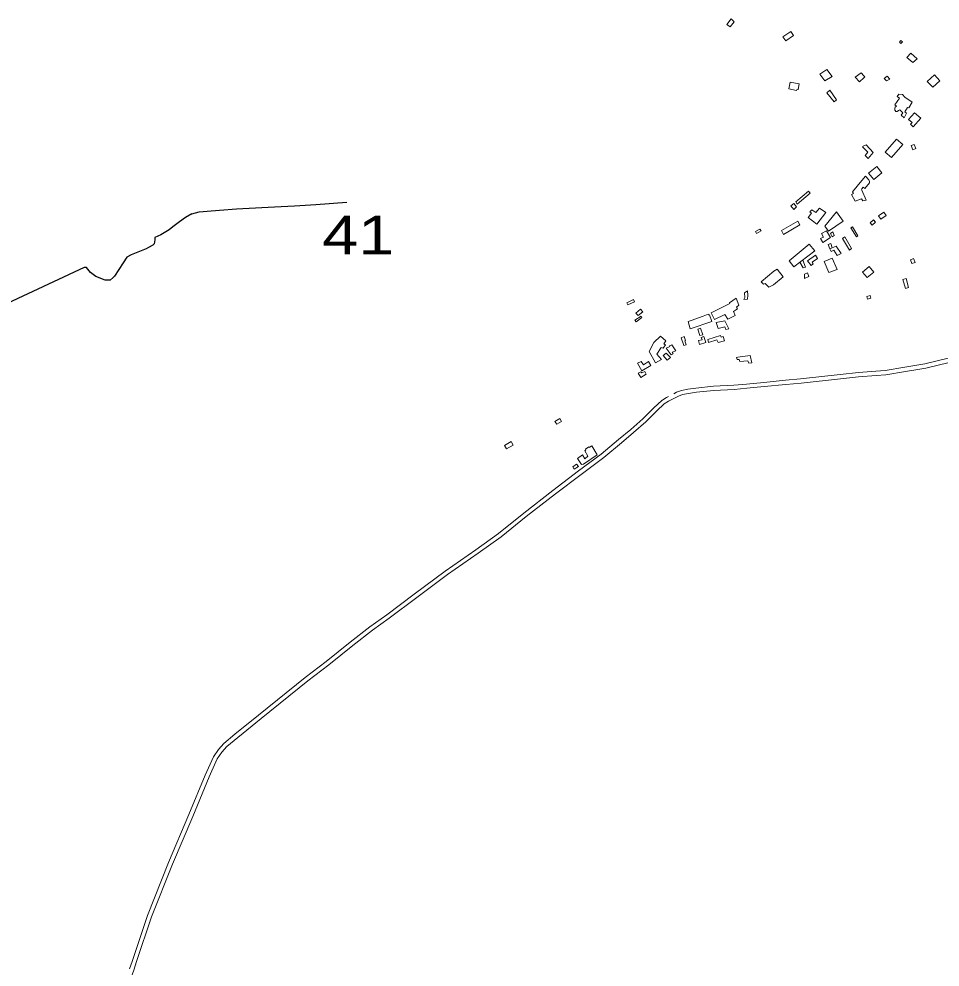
# Model space of a CAD drawing. Extents: x 476989 to 498418, y 4381813 to 4416555.
# Drawn here: x 484337 to 485528, y 4384128 to 4385354 of the extents above; entities that cross this region are included whole.
import ezdxf
from ezdxf.enums import TextEntityAlignment as Align

# ---------------------------------------------------------------- set-up
doc = ezdxf.new("R2010")
doc.units = 0
doc.header["$LTSCALE"] = 20
for name, color, linetype, lineweight in [('13', 7, 'Continuous', 13), ('36', 7, 'Continuous', 13), ('47', 7, 'Continuous', 13), ('6', 7, 'Continuous', 25)]:
    doc.layers.add(name, color=color, linetype=linetype, lineweight=lineweight)

msp = doc.modelspace()

# ---------------------------------------------------------------- linework, layer by layer
at = {"layer": '36'}
for points in [[(485422.69, 4384896.4), (485445.04, 4384898.28), (485457.06, 4384899.22), (485464.89, 4384900.34), (485474.69, 4384902.21), (485508.34, 4384907.79), (485538.44, 4384915.04), (485558.81, 4384919.82), (485586.93, 4384924.38), (485601.44, 4384927.38)], [(485422.62, 4384890.78), (485445.5, 4384892.7), (485457.67, 4384893.65), (485465.81, 4384894.8), (485475.68, 4384896.69), (485509.45, 4384902.29), (485539.74, 4384909.58)], [(484710.84, 4384497.83), (484737.94, 4384518.74), (484768.95, 4384543.65), (484794.34, 4384563.28), (484815.94, 4384578.76), (484851.61, 4384605.75), (484891.48, 4384635.27), (484931.04, 4384662.95), (484960.7, 4384684.23), (484993.21, 4384710.28), (485030.75, 4384739.64), (485063.92, 4384764.85), (485093.47, 4384786.49), (485116.03, 4384805.54), (485131.93, 4384818.81), (485147.77, 4384832.69), (485161.73, 4384847.04), (485171.53, 4384855.86), (485177.07, 4384859.62), (485182.06, 4384861.97), (485189.79, 4384866.01), (485195.1, 4384868.19), (485202.95, 4384869.58), (485213.04, 4384870.95), (485235.55, 4384873.26), (485261.75, 4384874.66), (485278.18, 4384876.14), (485300.64, 4384878.33), (485328.67, 4384881.11), (485348.27, 4384882.97), (485399.25, 4384888.59), (485422.62, 4384890.78)], [(485183.89, 4384869.09), (485187.49, 4384870.96), (485193.57, 4384873.46), (485202.11, 4384874.97), (485212.4, 4384876.37), (485235.13, 4384878.7), (485261.36, 4384880.1), (485277.67, 4384881.57), (485300.11, 4384883.76), (485328.15, 4384886.54), (485347.71, 4384888.4), (485398.68, 4384894.02), (485422.69, 4384896.4)], [(484707.31, 4384502.21), (484734.52, 4384522.99), (484765.58, 4384547.94), (484791.08, 4384567.66), (484812.71, 4384583.16), (484848.35, 4384610.12), (484888.3, 4384639.7), (484927.89, 4384667.41), (484957.41, 4384688.58), (484989.83, 4384714.56), (485027.43, 4384743.96), (485060.66, 4384769.23), (485090.09, 4384790.79), (485112.52, 4384809.73), (485128.38, 4384822.96), (485144.01, 4384836.66), (485157.94, 4384850.98), (485168.16, 4384860.16), (485174.35, 4384864.37), (485176.85, 4384865.55)], [(484707.31, 4384502.21), (484647.11, 4384453.76), (484616.61, 4384429.19), (484602.17, 4384416.91), (484595.22, 4384409.32), (484588.71, 4384399.61), (484578.28, 4384375.87), (484557.06, 4384324.92), (484530.87, 4384263.12), (484503.59, 4384194.75), (484483.62, 4384135.07)], [(484710.84, 4384497.83), (484650.64, 4384449.38), (484620.19, 4384424.86), (484606.08, 4384412.85), (484599.65, 4384405.84), (484593.66, 4384396.89), (484583.45, 4384373.66), (484562.24, 4384322.74), (484536.06, 4384260.98), (484508.87, 4384192.82), (484489.54, 4384135.06)], [(484489.54, 4384135.06), (484485.82, 4384123.95), (484464.73, 4384064.76), (484456.32, 4384037.55), (484452.16, 4384022.11), (484445.88, 4383992.25), (484439.72, 4383943.85), (484434.59, 4383882), (484432.54, 4383857.52), (484431.34, 4383851.22), (484425.3, 4383828.91), (484409.87, 4383774.4), (484390.58, 4383702.73), (484376.62, 4383650.17), (484370.9, 4383630.79), (484368.78, 4383624.62), (484366.56, 4383620.22), (484360.54, 4383612.24), (484358.1, 4383609.8)], [(484483.62, 4384135.07), (484480.51, 4384125.78)]]:
    msp.add_lwpolyline(points, dxfattribs=at)
at = {"layer": '47'}
for p, q in [((485430.73, 4385278.66), (485429.6, 4385277.65)), ((485429.64, 4385279.89), (485430.73, 4385278.66)), ((485431.59, 4385150.48), (485427.01, 4385144.68))]:
    msp.add_line(p, q, dxfattribs=at)
for points in [[(485261.75, 4385350.07), (485256.55, 4385343.42), (485252.49, 4385346.53), (485257.99, 4385353.63)], [(485328.63, 4385325.22), (485324.86, 4385330.61), (485335.14, 4385337.31), (485338.56, 4385332.44)], [(485477.4, 4385325.79), (485479.27, 4385324.15), (485477.42, 4385322.04), (485475.55, 4385323.68)], [(485498.45, 4385302.23), (485490, 4385309.55), (485485.17, 4385303.97), (485492.83, 4385297.33)], [(485379.07, 4385273.78), (485372.7, 4385282.19), (485381.81, 4385288.09), (485388.5, 4385279.35)], [(485462.96, 4385275.95), (485458.57, 4385273.46), (485455.91, 4385276.72), (485459.56, 4385279.6)], [(485520.66, 4385281.5), (485511.38, 4385272.95), (485518.48, 4385265.25), (485527.76, 4385273.8)], [(485345.88, 4385269.62), (485344.44, 4385262.34), (485343.13, 4385262.81), (485342.47, 4385261.32), (485332.59, 4385263.42), (485334.26, 4385272.11)], [(485385.42, 4385261.39), (485394.28, 4385248.91), (485391.08, 4385246.45), (485381.82, 4385258.29)], [(485491.87, 4385246.19), (485482.36, 4385252.63), (485479.41, 4385256.13), (485474.53, 4385256.42), (485472.69, 4385253.22), (485475.36, 4385251.23), (485469.68, 4385242.53), (485471.61, 4385240.93), (485470.02, 4385239.75), (485469.7, 4385238.63), (485469.68, 4385237.51), (485469.66, 4385235.93), (485469.95, 4385235.1), (485470.91, 4385233.81), (485472.33, 4385233.94), (485474.23, 4385235.19), (485476.05, 4385236.29), (485479.89, 4385232.48), (485477.67, 4385229.44), (485481.67, 4385225.85), (485484.68, 4385231.74), (485482.54, 4385233.72), (485485.91, 4385239.08), (485487.71, 4385238.75)], [(485502.9, 4385225.4), (485493.14, 4385214.36), (485489.67, 4385217.42), (485491.81, 4385219.85), (485487.35, 4385223.77), (485494.77, 4385232.21)], [(485471.75, 4385198.38), (485457.07, 4385181.29), (485465.18, 4385174.32), (485479.86, 4385191.41)], [(485494.31, 4385191.46), (485496.54, 4385186.14), (485492.79, 4385184.57), (485490.56, 4385189.89)], [(485446.33, 4385162.95), (485435.67, 4385154.43), (485442.19, 4385146.28), (485452.85, 4385154.8)], [(485341.54, 4385117.13), (485358, 4385131.01), (485359.88, 4385128.25), (485343.44, 4385114.36)], [(485335.12, 4385111.93), (485338.88, 4385107.2), (485342.55, 4385110.64), (485339.07, 4385115.06)], [(485357.51, 4385097.15), (485368.62, 4385088.17), (485380.36, 4385103.26), (485372.01, 4385109.03), (485367.56, 4385103.58), (485362.09, 4385107.01), (485359.66, 4385104.07), (485361.62, 4385102.4)], [(485379.23, 4385085.92), (485383.64, 4385079.14), (485402.54, 4385092.1), (485394.26, 4385104.11)], [(485458.4, 4385099.53), (485451.27, 4385094.65), (485448.34, 4385098.92), (485455.47, 4385103.8)], [(485346.7, 4385087.36), (485344.04, 4385092.2), (485323.12, 4385080.13), (485325.71, 4385075.16)], [(485414.69, 4385084.77), (485421.67, 4385073.34), (485420.02, 4385071.95), (485412.62, 4385083.7)], [(485444.62, 4385090.94), (485440.26, 4385087.1), (485437.78, 4385089.92), (485442.14, 4385093.76)], [(485290.74, 4385076.25), (485296.71, 4385079.76), (485295.04, 4385081.98), (485289.22, 4385078.94)], [(485376.42, 4385064.78), (485386.3, 4385071.05), (485380.99, 4385079.78), (485374.59, 4385076.18), (485377.22, 4385071.74), (485373.36, 4385069.71)], [(485386.27, 4385076.22), (485388.49, 4385071.93), (485391.18, 4385073.68), (485389.36, 4385078.3)], [(485401.88, 4385069.6), (485410.97, 4385054.66), (485413.3, 4385056.85), (485404.78, 4385072.14)], [(485332.83, 4385040.86), (485358.81, 4385062.46), (485366.1, 4385053.67), (485338.95, 4385033.1)], [(485400.09, 4385050.6), (485393.57, 4385059.83), (485385.55, 4385056.3), (485387.34, 4385053.1), (485390.5, 4385054.62), (485394.78, 4385047.66)], [(485356.66, 4385040.89), (485366.9, 4385048.44), (485369.63, 4385044), (485362.81, 4385039.04), (485363.91, 4385036.96), (485361.23, 4385035.02)], [(485378.19, 4385039.92), (485388.72, 4385044.18), (485394.8, 4385029.82), (485384.25, 4385025.7)], [(485436.15, 4385033.44), (485427.79, 4385026.2), (485433.84, 4385019.21), (485442.2, 4385026.45)], [(485489.62, 4385042.13), (485493.73, 4385043.77), (485495.65, 4385038.96), (485491.54, 4385037.32)], [(485317.22, 4385029.98), (485325.37, 4385020.45), (485312.51, 4385010.01), (485306.62, 4385006.83), (485301.81, 4385011.58), (485299.61, 4385010.55), (485296.92, 4385013.86), (485313.3, 4385027.75)], [(485356.54, 4385025.58), (485358.36, 4385020.59), (485352.67, 4385018.3), (485352.65, 4385023.86)], [(485483.95, 4385017.97), (485487.31, 4385006.49), (485483.24, 4385005.3), (485479.88, 4385016.78)], [(485275.35, 4384999.72), (485275.62, 4384993.72), (485274.51, 4384991.12), (485278.93, 4384991.49), (485279.63, 4384996.44), (485279.21, 4385002.07)], [(485131.88, 4384990.73), (485133.04, 4384987.96), (485124.38, 4384983.93), (485123.04, 4384986.67)], [(485232.24, 4384973.73), (485256.24, 4384985.71), (485255.64, 4384986.42), (485264.26, 4384992.64), (485267.98, 4384983.55), (485264.85, 4384980.92), (485265.96, 4384978.66), (485260.82, 4384975.22), (485262.98, 4384970.42), (485253.45, 4384965.37), (485249.92, 4384971.55), (485236.63, 4384965.07)], [(485434.27, 4384991.29), (485438.67, 4384992.73), (485437.56, 4384996.12), (485433.16, 4384994.68)], [(485134.96, 4384973.48), (485137.8, 4384970.26), (485143.62, 4384975.18), (485140.65, 4384978.64)], [(485202.26, 4384962.64), (485205.11, 4384952.88), (485232.87, 4384962.57), (485229.87, 4384971.23), (485228.85, 4384971.04), (485228.23, 4384972.06), (485221.76, 4384969.24), (485206.44, 4384963.71)], [(485135.13, 4384962.27), (485133.6, 4384964.2), (485141.49, 4384969.44), (485142.72, 4384967.81)], [(485241.19, 4384953.59), (485238.74, 4384961.16), (485249.91, 4384963.4), (485255.04, 4384953.22), (485251.01, 4384952.26), (485249.57, 4384955.39)], [(485218.26, 4384953.88), (485221.3, 4384945.37), (485217.52, 4384944.38), (485214.88, 4384952.63)], [(485166.54, 4384943.66), (485173.38, 4384937.5), (485170.74, 4384933.52), (485172.96, 4384932.16), (485170.02, 4384927.89), (485167.44, 4384928.93), (485161.73, 4384920.25), (485168.12, 4384913.52), (485160.35, 4384908.85), (485151.84, 4384923.7), (485158.04, 4384935.36)], [(485196.83, 4384931.59), (485193.55, 4384941.49), (485197.01, 4384942.93), (485198.74, 4384937.86), (485198.11, 4384937.64), (485199.61, 4384932.22)], [(485222.65, 4384942.91), (485225.26, 4384935.23), (485216.88, 4384932.94), (485215.88, 4384937.84), (485220.3, 4384938.94), (485219.08, 4384941.85)], [(485249.49, 4384937.5), (485241.12, 4384935.21), (485239.52, 4384938.69), (485228.76, 4384935.35), (485227.77, 4384939.36), (485244.05, 4384944.48), (485244.89, 4384942.19), (485247.54, 4384943.11)], [(485186.49, 4384924.62), (485181.37, 4384932.42), (485178.47, 4384930.93), (485178.71, 4384930.27), (485174.01, 4384928), (485180.62, 4384919.36), (485183.12, 4384920.9), (485181.75, 4384922.86)], [(485142.63, 4384898.78), (485154.08, 4384905.6), (485151.02, 4384910.61), (485144.58, 4384906.61), (485141.69, 4384910.99), (485137.02, 4384908.61)], [(485174.13, 4384921.38), (485179.41, 4384916.01), (485175.21, 4384912.35), (485170.29, 4384918.41)], [(485266.7, 4384916.2), (485282.71, 4384918.56), (485284.62, 4384909.24), (485280.59, 4384908.66), (485279.6, 4384911.79), (485269.14, 4384910.81), (485268.41, 4384913.55), (485265.87, 4384913.33), (485264.93, 4384915.83)], [(485137.57, 4384895.7), (485141.36, 4384889.94), (485148.18, 4384894.62), (485146.28, 4384897.8), (485142.69, 4384896.02), (485141.37, 4384897.6)], [(485038.74, 4384833.32), (485032.85, 4384829.56), (485030.27, 4384833.1), (485036.4, 4384836.94)], [(484964.87, 4384802.3), (484967.76, 4384797.99), (484976.23, 4384802.68), (484973.49, 4384807.16)], [(485077.7, 4384801.78), (485084.8, 4384790.17), (485067.22, 4384778.07), (485064.7, 4384777.53), (485059.16, 4384785.44), (485065.69, 4384789.96), (485068.86, 4384784.97), (485072.67, 4384788.24), (485068.78, 4384795.47), (485070.08, 4384796.6), (485069.91, 4384797.28), (485073.98, 4384800.36), (485074.47, 4384799.7)], [(485058.21, 4384777.93), (485060.61, 4384775.18), (485055.1, 4384771.73), (485053.37, 4384774.59)]]:
    msp.add_lwpolyline(points, close=True, dxfattribs=at)
for points in [[(485429.64, 4385279.89), (485426.15, 4385283.84), (485418.4, 4385278.2), (485423.65, 4385272.41), (485429.6, 4385277.65)], [(485427.86, 4385188.7), (485432.25, 4385191), (485441.64, 4385181.18)], [(485441.64, 4385181.18), (485434.85, 4385173.17), (485431, 4385177.06), (485434.44, 4385181.58), (485427.86, 4385188.36)], [(485427.01, 4385144.68), (485414.85, 4385130.05), (485416.09, 4385128.19), (485413.43, 4385126.89), (485418.24, 4385117.89), (485426.55, 4385121.28)], [(485426.79, 4385133.81), (485428.39, 4385136.27), (485430.92, 4385134.66), (485436.72, 4385141.78), (485436.75, 4385143.51), (485435.88, 4385145.77), (485431.59, 4385150.48)], [(485426.76, 4385132.14), (485426.34, 4385133.12), (485426.79, 4385133.81)], [(485426.55, 4385121.28), (485428.06, 4385118.42), (485432.65, 4385119.55), (485426.76, 4385132.14)], [(485385.55, 4385056.3), (485383.4, 4385062.17), (485386.75, 4385063.22), (485388.34, 4385057.54)], [(485350.4, 4385041.78), (485353.89, 4385032.82), (485350.82, 4385031.71), (485346.73, 4385039)]]:
    msp.add_lwpolyline(points, dxfattribs=at)
at = {"layer": '6'}
msp.add_line((484721.33, 4385113.65), (484761.13, 4385116.93), dxfattribs=at)
for points in [[(484560.92, 4385101.66), (484570.5, 4385104.22), (484580.6, 4385105.21), (484596.61, 4385106.51), (484618.44, 4385108.14), (484667.62, 4385110.91), (484693.66, 4385111.99), (484721.33, 4385113.65)], [(484560.92, 4385101.66), (484552.79, 4385097.07), (484544.91, 4385091.31), (484536.45, 4385084.76), (484531.54, 4385081.19), (484520.76, 4385074.46), (484512.97, 4385071.07)], [(484512.97, 4385071.07), (484512.88, 4385067.92), (484512.1, 4385063.1), (484510.53, 4385061.38), (484505.04, 4385058.19), (484501.9, 4385056.36), (484482.31, 4385048.73), (484476.84, 4385045.76), (484472.32, 4385038.32), (484460.76, 4385021.04), (484459.08, 4385019.18)], [(484459.08, 4385019.18), (484455.39, 4385016.01), (484448.82, 4385016.01), (484436.64, 4385020.7), (484429.76, 4385025.69), (484424.76, 4385032.25), (484421.64, 4385032.25), (484282.12, 4384967.05), (484265.88, 4384959.56), (484249.94, 4384952.38), (484246.29, 4384952.07), (484240.98, 4384954.25), (484237.23, 4384962.37)]]:
    msp.add_lwpolyline(points, dxfattribs=at)

# ---------------------------------------------------------------- texts
at = {"layer": '13', "width": 1.25}
msp.add_text('41', height=50, dxfattribs=at).set_placement((484775.97, 4385049.16), align=Align.CENTER)

doc.saveas('drawing.dxf')
